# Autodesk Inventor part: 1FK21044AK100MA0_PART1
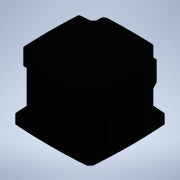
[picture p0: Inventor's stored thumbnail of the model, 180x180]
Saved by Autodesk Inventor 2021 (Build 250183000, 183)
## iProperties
Created: 2025-04
Part Number: 1FK21044AK100MA0_PART1
Material: Generic
Catalog Web Link: www.3dfindit.com
Description: -Servo synchronous motor
Document SubType Name: Modeling
Designer: psAdmin
Mass: 314.393 g
Surface Area: 353.669 cm^2
Volume: 314.393 cm^3
Density: 1 g/cm^3
Appearance: PSOLRGB-176-176-176
Category: PARTsolutions
Title: 1FK21044AK100MA0_PART1
Author: Cadenas PARTsolutions
Comments: Servo synchronous motor
Sending System: PARTsolutions
Preprocessor: ST-DEVELOPER v19.3
PSOL_IDENT_0: {$CADENAS_DATA/23d-libs/siemens_ag/_cat_/5e/d8/1fk21044ak100ma0.prj},213 {VTYP=3D},{NB=1FK21044AK100
PSOL_IDENT_1: MA0_PART1},{LINA=1FK21044AK100MA0_PART1},{NN=1FK21044AK100MA0_PART1},{NOPRJ=TRUE},{DATE=19.08.2025 1
PSOL_IDENT_2: 4:00:41},{GEOMDATE=30.07.2025 02:00:53},{VERSION=},{LINEID=10},{WBVAR=},{WBNUMERIC=}  {NB=1FK21044AK
PSOL_IDENT_3: 100MA0_PART1},{LINA=1FK21044AK100MA0_PART1},{KT=DUMMY},{PREVIEW=../../../_pool_/cb/72/p_d211_xx_0043
PSOL_IDENT_4: 4j.png},{DESCSHORT=SIMOTICS S-1FK2 HD, SINAMICS S210 3AC 400V-480V, 0.95 Nm, 6000 rpm},{DESCLONG=SIM
PSOL_IDENT_5: OTICS S-1FK2 HD servo motor M0=1.27 Nm; PN = 0.6 kW at nN=6000 rpm (380-480 V); PN = 0.4 kW at nN=30
PSOL_IDENT_6: 00 rpm (200-240 V); with holding brake; degree of protection IP64; cylindrical shaft D19x40mm; absol
PSOL_IDENT_7: ute encoder 22-bit + 12-bit multiturn (encoder AM22DQC); with OCC interface; plug size M17, rotatabl
PSOL_IDENT_8: e; SIMOTICS S-1FK2 servomotorfor a wide range of uses in industrial environments. SIMOTICS S‑1FK2 se
PSOL_IDENT_9: rvomotors are compact synchronous motors with a high dynamic performance that set themselves apart a
PSOL_IDENT_10: s a result of their high power density, degree of protection and overload capability. The motors are
PSOL_IDENT_11: available in two variants: as High Dynamic variant (highest dynamic performance as a result of the
PSOL_IDENT_12: low intrinsic moment of inertia for applications demanding a high dynamic performance with low moved
PSOL_IDENT_13: masses) - and as Compact variant (precise and stable closed-loop control for medium up to large mov
PSOL_IDENT_14: ed masses as a result of a medium intrinsic moment of inertia). SIMOTICSS‑1FK2 servomotors fully exp
PSOL_IDENT_15: loit their strengths in a system with the SINAMICSS210 frequency converter and simple connection usi
PSOL_IDENT_16: ng the one cable connection (OCC). Advantages include the short control and positioning times, fast
PSOL_IDENT_17: and precise correction of disturbing quantities as well as stable control with a high dynamic perfor
PSOL_IDENT_18: mance. The servo motors can be configured to address a wide range of requirements. For example with
PSOL_IDENT_19: and without holding brake, IP64 or IP65 degree of protection, singleturn or multiturn absolute encod
PSOL_IDENT_20: ers - to name just a few. Further, the servomotors are available in different shaft heights extendin
PSOL_IDENT_21: g from 20 to 100. A shaft sealing ring is available to achieve an IP65 degree of protection and for
PSOL_IDENT_22: subsequent mounting at the motor or as spare part. SIMOTICS - the optimum motor for each and every m
PSOL_IDENT_23: otion control application.},{INTNO=804766910005},{SUPPLIERALTNO=1FK2104-4AK10-0MA0},{MANUID=1FK21044
PSOL_IDENT_24: AK100MA0},{MANUNAME=Siemens},{MANUTYPEDESC=Synchronous motor 1FK2-HD 1,27 Nm},{AAU732=SIMOTICS},{AAO
PSOL_IDENT_25: 057=S-1FK2},{AAU734=SIMOTICS S-1FK2 HD servo motor M0=1.27 Nm; PN = 0.6 kW at nN=6000 rpm (380-480 V
PSOL_IDENT_26: ); PN = 0.4 kW at nN=3000 rpm (200-240 V); with holding brake; degree of protection IP64; cylindrica
PSOL_IDENT_27: l shaft D19x40mm; absolute encoder 22-bit + 12-bit multiturn (encoder AM22DQC); with OCC interface;
PSOL_IDENT_28: plug size M17, rotatable;},{AAW338=Synchronous motor 1FK2-HD 1,27 Nm},{AAO742=SIMOTICS},{AAO663=4042
PSOL_IDENT_29: 948691076},{NOCUPEROU=1},{PRICEQUANTITY=1},{QUANTITYMIN=1},{QUANTITYINT=1},{CTN=85015100},{COO=DE},{
PSOL_IDENT_30: AAO676=1FK2104-4AK10-0MA0},{AAO677=Siemens AG},{ORDERUNIT=C62},{CONTENTUNIT=C62}
NB: 1FK21044AK100MA0_PART1
NT: Servo synchronous motor
NBSYN: $MANUID._PART1
LINA: 1FK21044AK100MA0_PART1
CATALOG: SIEMENS
PREVIEW: ../../../_pool_/cb/72/p_d211_xx_00434j.png
DESCSHORT: SIMOTICS S-1FK2 HD, SINAMICS S210 3AC 400V-480V, 0.95 Nm, 6000 rpm
DESCLONG: SIMOTICS S-1FK2 HD servo motor M0=1.27 Nm; PN = 0.6 kW at nN=6000 rpm (380-480 V); PN = 0.4 kW at nN=3000 rpm (200-240 V); with holding brake; degree of protect
INTNO: 804766910005
SUPPLIERALTNO: 1FK2104-4AK10-0MA0
MANUID: 1FK21044AK100MA0
MANUNAME: Siemens
MANUTYPEDESC: Synchronous motor 1FK2-HD 1,27 Nm
AAU732: SIMOTICS
AAO057: S-1FK2
AAU734: SIMOTICS S-1FK2 HD servo motor M0=1.27 Nm; PN = 0.6 kW at nN=6000 rpm (380-480 V); PN = 0.4 kW at nN=3000 rpm (200-240 V); with holding brake; degree of protect
AAW338: Synchronous motor 1FK2-HD 1,27 Nm
AAO742: SIMOTICS
AAO663: 4042948691076.0
NOCUPEROU: 1
PRICEQUANTITY: 1
QUANTITYMIN: 1
QUANTITYINT: 1
CTN: 85015100
COO: DE
ARTICLENO: 1FK21044AK100MA0_PART1
BOMINFO: 1FK21044AK100MA0_PART1
CREATOR: CADENAS GmbH
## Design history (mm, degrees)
feature "2025_04_17_15_35_41_0812"
node "ECLASS_CAX_IMPORTER_001_CP_0_XY"
node "ECLASS_CAX_IMPORTER_001_CP_0_YZ"
node "ECLASS_CAX_IMPORTER_001_CP_0_ZX"
node "ECLASS_CAX_IMPORTER_001_CP_0_X"
node "ECLASS_CAX_IMPORTER_001_CP_0_Y"
node "ECLASS_CAX_IMPORTER_001_CP_0_Z"
node "ECLASS_CAX_IMPORTER_001_CP_0_Center"
node "ECLASS_CAX_IMPORTER_001_CP_1_XY"
node "ECLASS_CAX_IMPORTER_001_CP_1_YZ"
node "ECLASS_CAX_IMPORTER_001_CP_1_ZX"
node "ECLASS_CAX_IMPORTER_001_CP_1_X"
node "ECLASS_CAX_IMPORTER_001_CP_1_Y"
node "ECLASS_CAX_IMPORTER_001_CP_1_Z"
node "ECLASS_CAX_IMPORTER_001_CP_1_Center"
body "Solid1"
